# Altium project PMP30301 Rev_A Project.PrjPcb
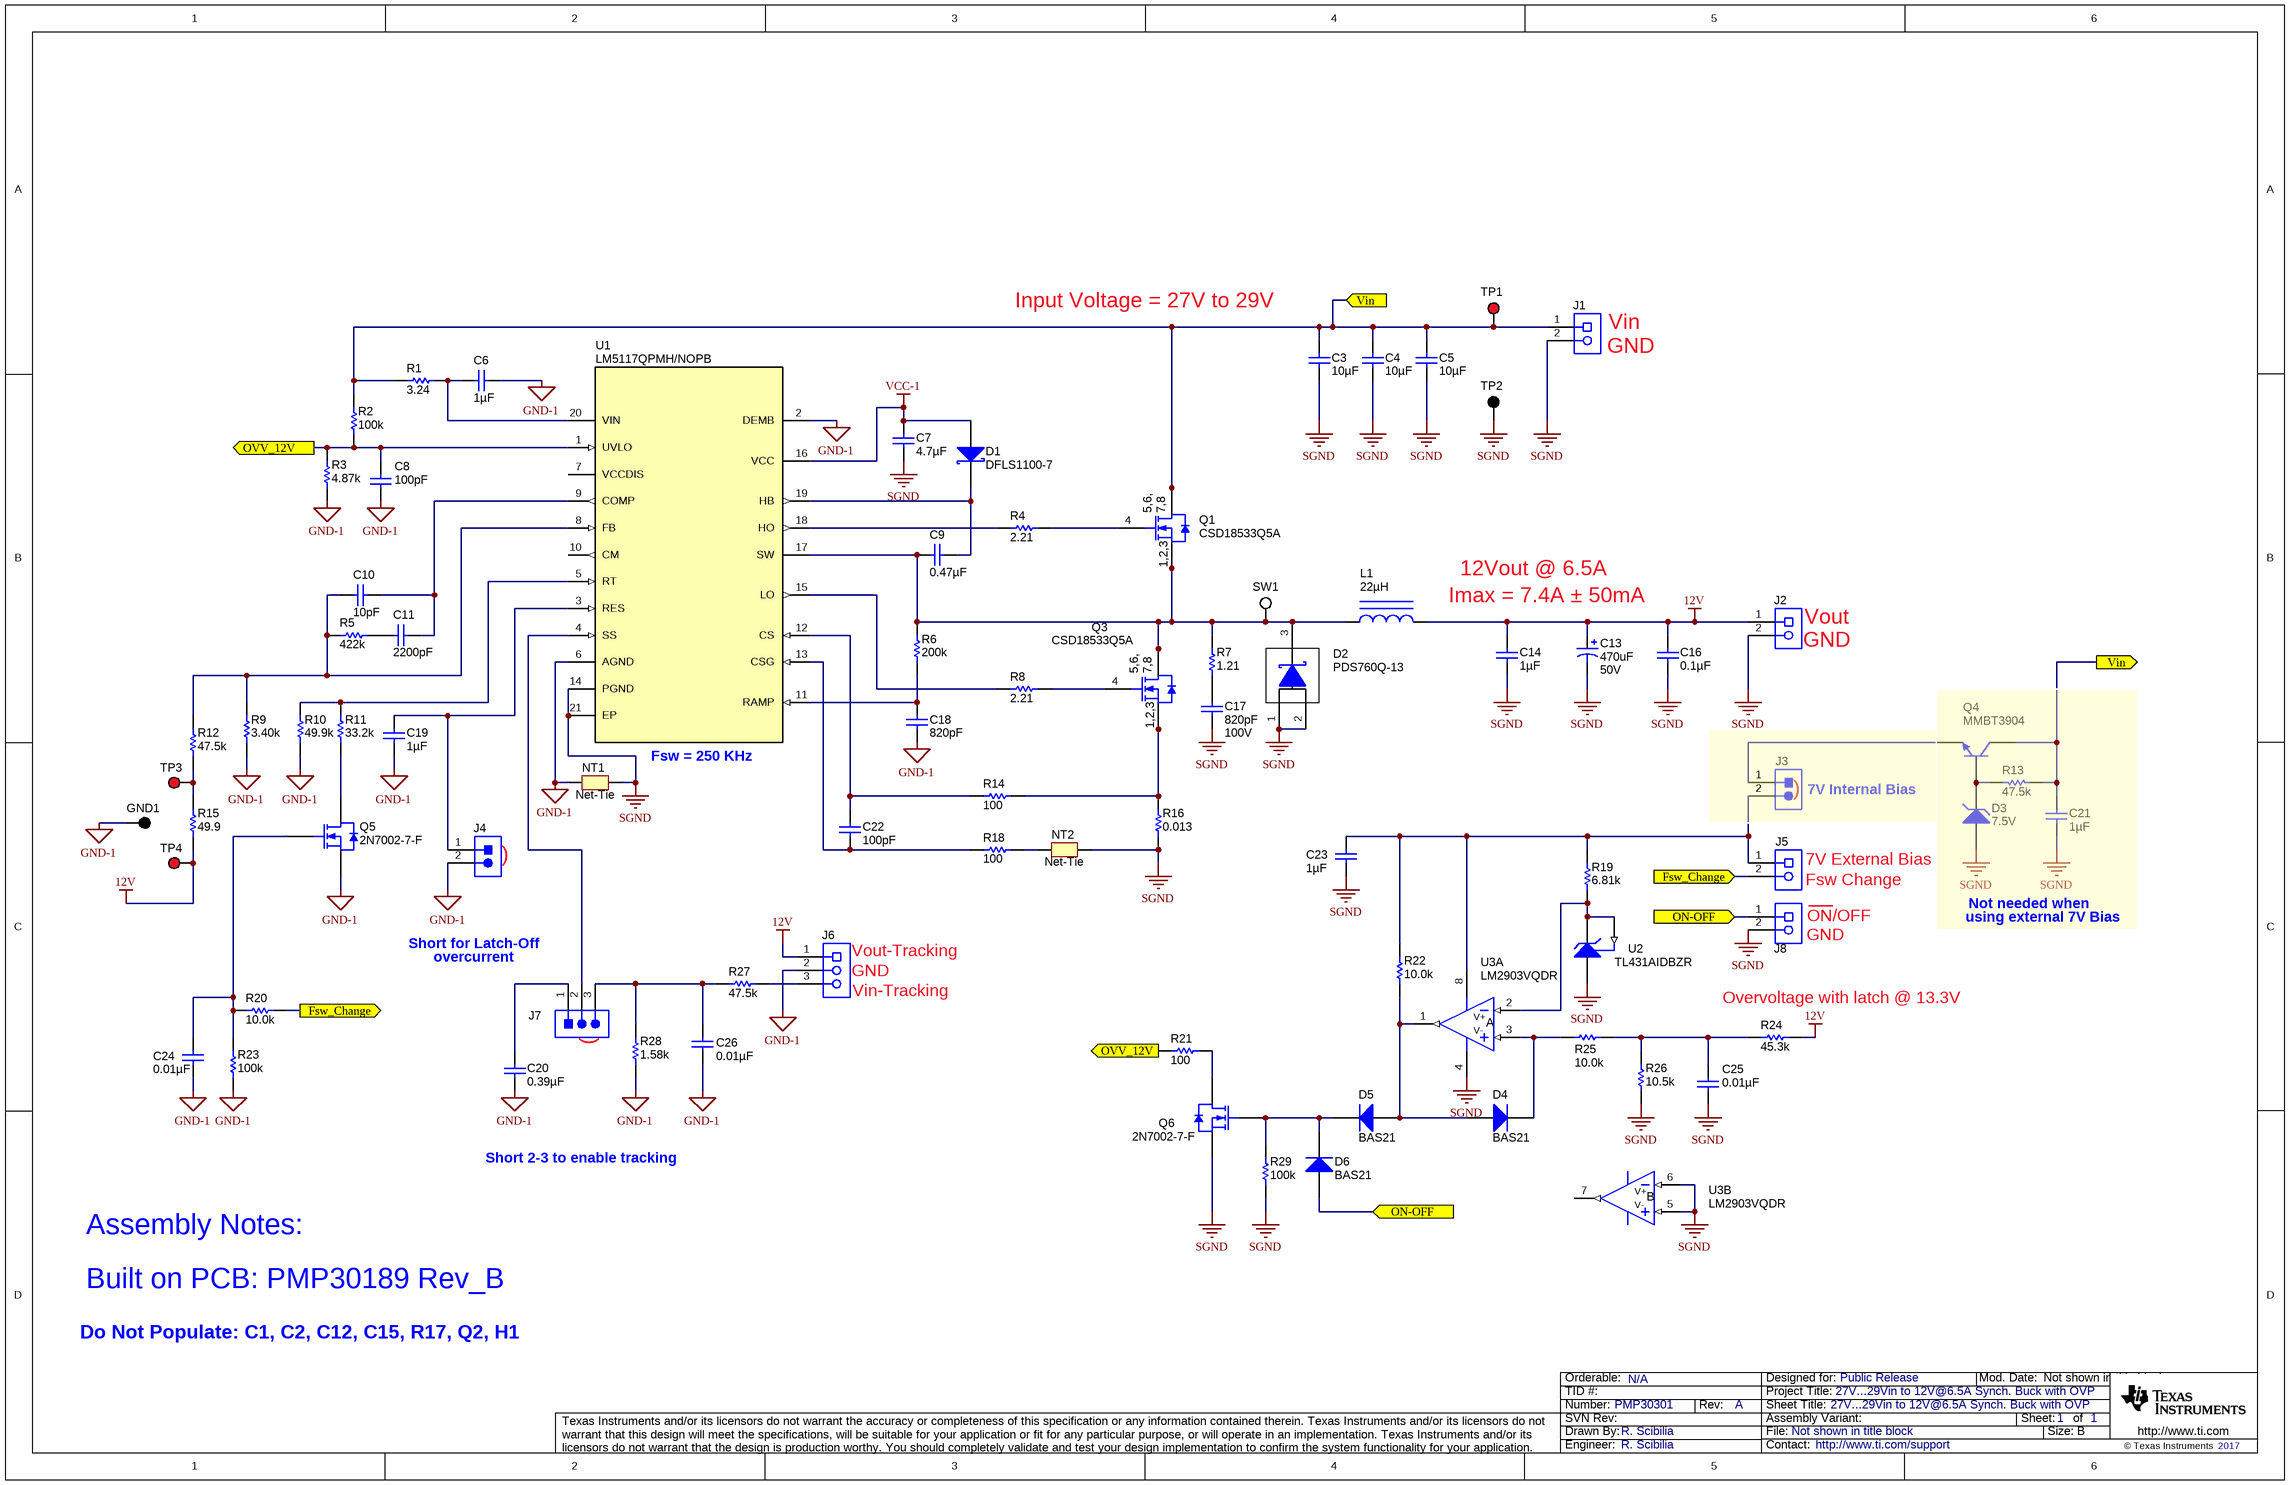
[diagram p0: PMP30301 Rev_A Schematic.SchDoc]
CopyrightYear: 2017; EVM_Orderable: N/A; PCB_Layout: PMP30189 Rev_B; PCB_Rev: B; PRJ_Customer: Public Release; PRJ_Engineer: R. Scibilia; PRJ_Number: PMP30301; PRJ_Title: 27V...29Vin to 12V@6.5A Synch. Buck with OVP; SCH_Rev: A; TechSupport: http://www.ti.com/support
1 sheet, 81 parts. Net scope: flat (ports and power ports of the same name join across sheets).
Board file: PMP30189 Rev_B PCB.PcbDoc

## Sheet PMP30301 Rev_A Schematic.SchDoc: 27V...29Vin to 12V@6.5A Synch. Buck with OVP
size 431 x 279 mm; Date: Not shown in title block; ApprovedBy: Not shown in title block; CheckedBy: Not shown in title block; Author: Not shown in title block; CompanyName: Not shown in title block; DrawnBy: R. Scibilia; Engineer: Not shown in title block; Organization: Not shown in title block; Address1: Not shown in title block; Address2: Not shown in title block; Address3: Not shown in title block; Address4: Not shown in title block; DocumentNumber: 1; Revision: Use project parameter SCH_Rev; SheetNumber: 1; SheetTotal: 1; PageSetup: Record=PageOptions¦CenterHorizontal=True¦CenterVertical=True¦PrintScale=1.00¦XCorrection=1.00¦YCorrection=1.00¦PrintKind=0¦BorderSize=5000000¦LeftOffset=0¦BottomOffset=0¦Orientation=2¦PaperLength=1000¦PaperWidth=1000¦Scale=100¦PaperSource=15¦PrintQuality=-3¦MediaType=1¦DitherType=10¦PrintScaleMode=1¦PaperKind=Letter¦PaperIndex=1

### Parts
C3  ValueDisplayed: 10µF  [1210_280]  (hidden comment: C3225X7R1H106M250AC)
C4  ValueDisplayed: 10µF  [1210_280]  (hidden comment: C3225X7R1H106M250AC)
C5  ValueDisplayed: 10µF  [1210_280]  (hidden comment: C3225X7R1H106M250AC)
C6  ValueDisplayed: 1µF  [1206]  (hidden comment: GRM31MR71H105KA88L)
C7  ValueDisplayed: 4.7µF  [0805_HV]  (hidden comment: GRM21BR71C475KA73L)
C8  ValueDisplayed: 100pF  [0603]  (hidden comment: 06035A101FAT2A)
C9  ValueDisplayed: 0.47µF  [0603]  (hidden comment: GRM188R71E474KA12D)
C10  ValueDisplayed: 10pF  [0603]  (hidden comment: GRM1885C1H100JA01D)
C11  ValueDisplayed: 2200pF  [0805_HV]  (hidden comment: GRM2165C1H222JA01D)
C13  value 470uF  Value2: 50V  [ZLH_1250x2500]  (hidden comment: 50ZLH470M12.5X20)
C14  ValueDisplayed: 1µF  [0805_HV]  (hidden comment: 08055C105KAT2A)
C16  ValueDisplayed: 0.1µF  [0805_HV]  (hidden comment: 08055C104JAT2A)
C17  value 820pF  Value2: 100V  [0603]  (hidden comment: GRM188R72A821KA01D)
C18  ValueDisplayed: 820pF  [0603]  (hidden comment: GRM1885C1H821JA01D)
C19  ValueDisplayed: 1µF  [0603]  (hidden comment: C1608X7R1C105K080AC)
C20  ValueDisplayed: 0.39µF  [0603]  (hidden comment: GRM188R71C394KA88D)
C21  ValueDisplayed: 1µF  [0805_HV]  (hidden comment: 08055C105KAT2A)
C22  ValueDisplayed: 100pF  [0603L]  (hidden comment: GRM1885C1H101JA01D)
C23  ValueDisplayed: 1µF  [0603]  (hidden comment: C1608X7R1C105K080AC)
C24  ValueDisplayed: 0.01µF  [0603]  (hidden comment: 06031C103JAT2A)
C25  ValueDisplayed: 0.01µF  [0603]  (hidden comment: 06031C103JAT2A)
C26  ValueDisplayed: 0.01µF  [0603]  (hidden comment: 06031C103JAT2A)
D1  DFLS1100-7  [powerDI123]
D2  PDS760Q-13  [PowerDI5]
D3  value 7.5V  [SOD-323F]  (hidden comment: MM3Z7V5B)
D4  value BAS21  [SOT-23L]  (hidden comment: BAS21-TP)
D5  value BAS21  [SOT-23L]  (hidden comment: BAS21-TP)
D6  value BAS21  [SOT-23L]  (hidden comment: BAS21-TP)
GND1  5001  [Keystone5001]  (value not drawn)
J1  1732720  [Phoenix_1732720]  (value not drawn)
J2  1732720  [Phoenix_1732720]  (value not drawn)
J3  800-10-002-10-001000  [Mill-Max_800-10-002-10-001000]  (value not drawn)
J4  800-10-002-10-001000  [Mill-Max_800-10-002-10-001000]  (value not drawn)
J5  39357-0002  [Molex_39357-0002]  (value not drawn)
J6  39357-0003  [Molex_39357-0003]  (value not drawn)
J7  800-10-003-10-001000  [Mill-Max_800-10-003-10-001000]  (value not drawn)
J8  39357-0002  [Molex_39357-0002]  (value not drawn)
L1  ValueDisplayed: 22µH  [WE-HCF_2013]  (hidden comment: 7443632200)
NT1  Net-Tie  [Net-Tie_10mil]  (net tie, no BOM)
NT2  Net-Tie  [Net-Tie_10mil]  (net tie, no BOM)
Q1  CSD18533Q5A  [DQJ0008A]
Q3  CSD18533Q5A  [DQJ0008A]
Q4  value MMBT3904  [SOT-23]  (hidden comment: MMBT3904LT1G)
Q5  2N7002-7-F  [SOT-23]
Q6  2N7002-7-F  [SOT-23]
R1  value 3.24  [0603]  (hidden comment: CRCW06033R24FKEA)
R2  ValueDisplayed: 100k  [0603]  (hidden comment: CRCW0603100KFKEA)
R3  ValueDisplayed: 4.87k  [0603]  (hidden comment: RC0603FR-074K87L)
R4  ValueDisplayed: 2.21  [0805_HV]  (hidden comment: RC0805FR-072R21L)
R5  ValueDisplayed: 422k  [0603]  (hidden comment: RC0603FR-07422KL)
R6  ValueDisplayed: 200k  [0603]  (hidden comment: RC0603FR-07200KL)
R7  value 1.21  [0805_HV]  (hidden comment: CRCW08051R21FKEA)
R8  ValueDisplayed: 2.21  [0805_HV]  (hidden comment: RC0805FR-072R21L)
R9  ValueDisplayed: 3.40k  [0603]  (hidden comment: RC0603FR-073K4L)
R10  ValueDisplayed: 49.9k  [0603]  (hidden comment: RC0603FR-0749K9L)
R11  ValueDisplayed: 33.2k  [0603]  (hidden comment: RC0603FR-0733K2L)
R12  ValueDisplayed: 47.5k  [0603]  (hidden comment: RC0603FR-0747K5L)
R13  ValueDisplayed: 47.5k  [0603]  (hidden comment: RC0603FR-0747K5L)
R14  ValueDisplayed: 100  [0603]  (hidden comment: RC0603FR-07100RL)
R15  ValueDisplayed: 49.9  [0603]  (hidden comment: RC0603FR-0749R9L)
R16  ValueDisplayed: 0.013  [0612]  (hidden comment: PRL1632-R013-F-T1)
R18  ValueDisplayed: 100  [0603]  (hidden comment: RC0603FR-07100RL)
R19  ValueDisplayed: 6.81k  [0603]  (hidden comment: RC0603FR-076K81L)
R20  ValueDisplayed: 10.0k  [0603]  (hidden comment: CRCW060310K0FKEA)
R21  ValueDisplayed: 100  [0603]  (hidden comment: RC0603FR-07100RL)
R22  ValueDisplayed: 10.0k  [0603]  (hidden comment: CRCW060310K0FKEA)
R23  ValueDisplayed: 100k  [0603]  (hidden comment: CRCW0603100KFKEA)
R24  ValueDisplayed: 45.3k  [0603]  (hidden comment: RC0603FR-0745K3L)
R25  ValueDisplayed: 10.0k  [0603]  (hidden comment: CRCW060310K0FKEA)
R26  ValueDisplayed: 10.5k  [0603]  (hidden comment: RC0603FR-0710K5L)
R27  ValueDisplayed: 47.5k  [0603]  (hidden comment: RC0603FR-0747K5L)
R28  ValueDisplayed: 1.58k  [0603]  (hidden comment: RC0603FR-071K58L)
R29  ValueDisplayed: 100k  [0603]  (hidden comment: CRCW0603100KFKEA)
SW1  5002  [Keystone5002]  (value not drawn)
TP1  5000  [Keystone5000]  (value not drawn)
TP2  5001  [Keystone5001]  (value not drawn)
TP3  5000  [Keystone5000]  (value not drawn)
TP4  5000  [Keystone5000]  (value not drawn)
U1  LM5117QPMH/NOPB  [PWP0020A_N]
U2  TL431AIDBZR  [DBZ0003A_N]
U3  LM2903VQDR  [D0008A_N]  (parts A,B of 2)

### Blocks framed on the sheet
): J3

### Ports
Fsw_Change, ON-OFF, OVV_12V, Vin

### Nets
12V: C13.1(+) C14.1 C16.1 J2.1 J6.1 L1.2 R15.1 R24.2 TP4.1
GND-1: C6.2 C8.2 C18.2 C19.2 C20.2 C24.1 C26.1 GND1.1 J4.2 J6.2 NT1.1 Q5.2(S) R3.1 R9.1 R10.1 R23.1 R28.1 U1.2(DEMB) U1.6(AGND)
SGND: C3.2 C4.2 C5.2 C7.2 C13.2(-) C14.2 C16.2 C17.2 C21.2 C23.2 C25.1 D2.1(A) D2.2(A) D3.2(A) J1.2 J2.2 J8.2 NT1.2 NT2.2 Q6.2(S) R16.1 R26.1 R29.1 TP2.1 U1.14(PGND) U1.21(EP) U2.3(ANODE) U3.4(V-) U3.5(IN+) U3.6(IN-)
VCC-1: C7.1 D1.2(A) U1.16(VCC)
Fsw_Change: J5.2 R20.2 ; port Fsw_Change
ON-OFF: D6.1(A) J8.1 ; port ON-OFF
OVV_12V: C8.1 R2.1 R3.2 R21.2 U1.1(UVLO) ; port OVV_12V
Vin: C3.1 C4.1 C5.1 C21.1 J1.1 Q1.5(D) Q1.6(D) Q1.7(D) Q1.8(D) Q1.9(D) Q4.3(C) R1.1 R2.2 R13.2 TP1.1 ; port Vin
NetC6_1: C6.1 R1.2 U1.20(VIN)
NetC9_1: C9.1 D1.1(K) U1.19(HB)
NetC9_2: C9.2 D2.3(K) L1.1 Q1.1(S) Q1.2(S) Q1.3(S) Q3.5(D) Q3.6(D) Q3.7(D) Q3.8(D) Q3.9(D) R6.2 R7.2 SW1.1 U1.17(SW)
NetC10_1: C10.1 C11.1 U1.9(COMP)
NetC10_2: C10.2 R5.1 R9.2 R12.2 U1.8(FB)
NetC11_2: C11.2 R5.2
NetC17_1: C17.1 R7.1
NetC18_1: C18.1 R6.1 U1.11(RAMP)
NetC19_1: C19.1 J4.1 U1.3(RES)
NetC20_1: C20.1 J7.1
NetC22_1: C22.1 R14.1 U1.12(CS)
NetC22_2: C22.2 R18.1 U1.13(CSG)
NetC23_1: C23.1 J3.2 J5.1 R19.1 R22.1 U3.8(V+)
NetC24_2: C24.2 Q5.1(G) R20.1 R23.2
NetC25_2: C25.2 R24.1 R25.1 R26.2
NetC26_2: C26.2 J7.3 R27.2 R28.2
NetD3_1: D3.1(K) Q4.1(B) R13.1
NetD4_1: D4.1(A) D5.1(A) R22.2 U3.1(OUT)
NetD4_3: D4.3(K) R25.2 U3.3(IN+)
NetD5_3: D5.3(K) D6.3(K) Q6.1(G) R29.2
NetJ3_1: J3.1 Q4.2(E)
NetJ6_3: J6.3 R27.1
NetJ7_2: J7.2 U1.4(SS)
NetNT2_1: NT2.1 R18.2
NetQ1_4: Q1.4(G) R4.2
NetQ3_1: Q3.1(S) Q3.2(S) Q3.3(S) R14.2 R16.2
NetQ3_4: Q3.4(G) R8.2
NetQ5_3: Q5.3(D) R11.1
NetQ6_3: Q6.3(D) R21.1
NetR4_1: R4.1 U1.18(HO)
NetR8_1: R8.1 U1.15(LO)
NetR10_2: R10.2 R11.2 U1.5(RT)
NetR12_1: R12.1 R15.2 TP3.1
NetR19_2: R19.2 U2.1(CATHODE) U2.2(REF) U3.2(IN-)

Not connected (* = marked no-connect by the designer): U1 7(VCCDIS) 10(CM); U3 7(OUT)

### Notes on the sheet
- (near C3) Input Voltage = 27V to 29V
- (near J1) Vin
- (near J1) GND
- 12Vout @ 6.5A
- Imax = 7.4A ± 50mA
- (near J2) Vout
- (near J2) GND
- Fsw = 250 KHz
- (near J3) 7V Internal Bias
- (near J4) )
- Fsw Change
- (near J5) 7V External Bias
- Not needed when
- Short for Latch-Off
- overcurrent
- (near J6) GND
- (near J6) Vout-Tracking
- (near J8) GND
- ON/OFF
- using external 7V Bias
- (near J6) Vin-Tracking
- (near R24) Overvoltage with latch @ 13.3V
- (
- Short 2-3 to enable tracking
- Assembly Notes:
- Built on PCB: PMP30189 Rev_B
- Do Not Populate: C1, C2, C12, C15, R17, Q2, H1

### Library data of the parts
C3-C5 = C3225X7R1H106M250AC: CAP, CERM, 10 µF, 50 V, +/- 20%, X7R, 1210; Manufacturer: TDK; Polarized: N; CompType: Capacitor; Value: 10uF; U/M: EA; Cap_F: 0.00001; Tolerance_%: 20; Value1: Unknown; VDC_V: 50; Value2: 50V; TaMin_C: -55; TaMax_C: 125; Cap_Case: 1210; SizeArea_mm2: 8; SizeAreaWB_mm2: 14.7; SizeX_mm: 3.2; SizeY_mm: 2.5; SizeZ_mm: 2.8; AEC Category: Q200
C6 = GRM31MR71H105KA88L: CAP, CERM, 1 µF, 50 V, +/- 10%, X7R, 1206; Manufacturer: MuRata; Polarized: N; CompType: Capacitor; Value: 1uF; U/M: EA; Cap_F: 0.000001; Tolerance_%: 10; Value1: Unknown; VDC_V: 50; Value2: 50V; TaMin_C: -55; TaMax_C: 125
C7 = GRM21BR71C475KA73L: CAP, CERM, 4.7 µF, 16 V, +/- 10%, X7R, 0805; Manufacturer: MuRata; Polarized: N; CompType: Capacitor; Value: 4.7uF; U/M: EA; Cap_F: 0.0000047; Tolerance_%: 10; ESR_ohm: 0.006; Value1: 0.006 ohm; VDC_V: 16; Value2: 16V; TaMin_C: -55; TaMax_C: 125; Cap_Case: 0805; SizeArea_mm2: 2.5; SizeAreaWB_mm2: 6.75; SizeX_mm: 2; SizeY_mm: 1.25; SizeZ_mm: 1.45; AEC Category: Q200
C8 = 06035A101FAT2A: CAP, CERM, 100pF, 50V, +/-1%, C0G/NP0, 0603; Manufacturer: AVX; Polarized: N; CompType: Capacitor; U/M: EA; Cap_F: 0.0000000001; Tolerance_%: 1; Value1: Unknown; VDC_V: 50; TaMin_C: -55; TaMax_C: 125
C9 = GRM188R71E474KA12D: CAP, CERM, 0.47uF, 25V, +/-10%, X7R, 0603; Manufacturer: MuRata; Polarized: N; CompType: Capacitor; U/M: EA; Cap_F: 0.00000047; Tolerance_%: 10; Value1: Unknown; VDC_V: 25; TaMin_C: -55; TaMax_C: 125
C10 = GRM1885C1H100JA01D: CAP, CERM, 10 pF, 50 V, +/- 5%, C0G/NP0, 0603; Manufacturer: MuRata; Polarized: N; CompType: Capacitor; Value: 10pF; U/M: EA; Cap_F: 0.00000000001; Tolerance_%: 5; Value1: Unknown; VDC_V: 50; Value2: 50V; TaMin_C: -55; TaMax_C: 125; SizeArea_mm2: 1.28; SizeAreaWB_mm2: 4.68; SizeX_mm: 1.6; SizeY_mm: 0.8; SizeZ_mm: 1; AEC Category: Q200
C11 = GRM2165C1H222JA01D: CAP, CERM, 2200 pF, 50 V, +/- 5%, C0G/NP0, 0805; Manufacturer: MuRata; Polarized: N; CompType: Capacitor; Value: 2200pF; U/M: EA; Cap_F: 0.0000000022; Tolerance_%: 5; Value1: Unknown; VDC_V: 50; Value2: 50V; TaMin_C: -55; TaMax_C: 125; Cap_Case: 0805; SizeArea_mm2: 2.5; SizeAreaWB_mm2: 6.75; SizeX_mm: 2; SizeY_mm: 1.25; SizeZ_mm: 1.45; AEC Category: Q200
C13 = 63ZLH470M12.5X25: CAP, AL, 470 µF, 50 V, +/- 20%, 0.027 ohm, TH; Manufacturer: Rubycon; Polarized: Y; CompType: Capacitor; ValueDisplayed: 470µF; U/M: EA; Cap_F: 0.00047; Tolerance_%: 20; VDC_V: 50; ESR_ohm: 0.027; IRMS_A: 2.05; TaMin_C: -40; TaMax_C: 105; SizeAreaWB_mm2: 210.25; SizeArea_mm2: 156.25; SizeX_mm: 12.5; AEC Category: Q200
C14 C21 = 08055C105KAT2A: CAP, CERM, 1 µF, 50 V, +/- 10%, X7R, 0805; Manufacturer: AVX; Polarized: N; CompType: Capacitor; Value: 1uF; U/M: EA; Cap_F: 0.000001; Tolerance_%: 10; Value1: Unknown; VDC_V: 50; Value2: 50V; TaMin_C: -55; TaMax_C: 125; Cap_Case: 0805; SizeArea_mm2: 2.5; SizeAreaWB_mm2: 6.75; SizeX_mm: 2; SizeY_mm: 1.25; SizeZ_mm: 1.45; AEC Category: Q200
C16 = 08055C104JAT2A: CAP, CERM, 0.1uF, 50V, +/-5%, X7R, 0805; Manufacturer: AVX; Polarized: N; CompType: Capacitor; U/M: EA; Cap_F: 0.0000001; Tolerance_%: 5; ESR_Ohm: 0.024; Value1: 0.024 ohm; VDC_V: 50; TaMin_C: -55; TaMax_C: 125; Cap_Case: 0805
C17 = GRM188R72A821KA01D: CAP, CERM, 820 pF, 100 V, +/- 10%, X7R, 0603; Manufacturer: MuRata; Polarized: N; CompType: Capacitor; U/M: EA; Cap_F: 0.00000000082; Tolerance_%: 10; Value1: Unknown; VDC_V: 100; TaMin_C: -55; TaMax_C: 125; SizeArea_mm2: 1.28; SizeAreaWB_mm2: 4.68; SizeX_mm: 1.6; SizeY_mm: 0.8; SizeZ_mm: 1; AEC Category: Q200; Green_Lifecycle: Active; Green_REACh: Passed
C18 = GRM1885C1H821JA01D: CAP, CERM, 820 pF, 50 V, +/- 5%, C0G/NP0, 0603; Manufacturer: MuRata; Polarized: N; CompType: Capacitor; Value: 820pF; U/M: EA; Cap_F: 0.00000000082; Tolerance_%: 5; Value1: Unknown; VDC_V: 50; Value2: 50V; TaMin_C: -55; TaMax_C: 125; SizeArea_mm2: 1.28; SizeAreaWB_mm2: 4.68; SizeX_mm: 1.6; SizeY_mm: 0.8; SizeZ_mm: 1; AEC Category: Q200
C19 C23 = C1608X7R1C105K080AC: CAP, CERM, 1 µF, 16 V, +/- 10%, X7R, 0603; Manufacturer: TDK; Polarized: N; CompType: Capacitor; Value: 1uF; U/M: EA; Cap_F: 0.000001; Tolerance_%: 10; ESR_ohm: 0.0057; Value1: 0.0057 ohm; VDC_V: 16; Value2: 16V; TaMin_C: -55; TaMax_C: 125; SizeArea_mm2: 1.28; SizeAreaWB_mm2: 4.68; SizeX_mm: 1.6; SizeY_mm: 0.8; SizeZ_mm: 1; AEC Category: Q200
C20 = GRM188R71C394KA88D: CAP, CERM, 0.39 µF, 16 V, +/- 10%, X7R, 0603; Manufacturer: MuRata; Polarized: N; CompType: Capacitor; Value: 0.39uF; U/M: EA; Cap_F: 0.00000039; Tolerance_%: 10; Value1: Unknown; VDC_V: 16; Value2: 16V; TaMin_C: -55; TaMax_C: 125; SizeArea_mm2: 1.28; SizeAreaWB_mm2: 4.68; SizeX_mm: 1.6; SizeY_mm: 0.8; SizeZ_mm: 1; AEC Category: Q200
C22 = GRM1885C1H101JA01D: CAP, CERM, 100pF, 50V, +/-5%, C0G/NP0, 0603; Manufacturer: MuRata; Polarized: N; CompType: Capacitor; U/M: EA; Cap_F: 0.0000000001; Tolerance_%: 5; Value1: Unknown; VDC_V: 50; TaMin_C: -55; TaMax_C: 125; Cap_Case: 0603
C24-C26 = 06031C103JAT2A: CAP, CERM, 0.01 µF, 100 V, +/- 5%, X7R, 0603; Manufacturer: AVX; Polarized: N; CompType: Capacitor; Value: 0.01uF; U/M: EA; Cap_F: 0.00000001; Tolerance_%: 5; ESR_ohm: 0.098; Value1: 0.098 ohm; VDC_V: 100; Value2: 100V; TaMin_C: -55; TaMax_C: 125
D1 = DFLS1100-7: Diode, Schottky, 100V, 1A, PowerDI123; Manufacturer: Diodes Inc.; U/M: EA; Vf_V: 0.77; Value2: 0.77V; Io_A: 1; Vr_V: 100; TJmax_C: 175; RJC_CperW: 7
D2 = PDS560-13: Diode, Schottky, 60 V, 7 A, PowerDI5; Manufacturer: Diodes Inc.; U/M: EA; Vf_V: 0.67; Value1: 7A; Value2: 0.67V; Io_A: 5; Vr_V: 60; TJmax_C: 150; SizeAreaWB_mm2: 49.56; SizeArea_mm2: 24.96; SizeX_mm: 6.4; SizeY_mm: 3.9; SizeZ_mm: 1.05; AEC Category: Q101
D3 = MM3Z7V5B: Diode, Zener, 7.5 V, 200 mW, SOD-323F; Manufacturer: Fairchild Semiconductor; SymbolCreator: a0412235; U/M: EA; Power_W: 0.2; Vz_V: 7.5; Value1: 0.2W; RJA_CperW: 595; SizeAreaWB_mm2: 7.875; SizeArea_mm2: 3.125; SizeX_mm: 2.5; SizeY_mm: 1.25; SizeZ_mm: 0.8; AEC Category: Q101
D4-D6 = BAS21-TP: Diode, P-N, 200V, 200A, SOT-23; Manufacturer: Micro Commercial Components; U/M: EA; Vf_V: 1.25; Io_A: 200; Value2: 1.25V; TJmax_C: 150; RJC_CperW: 430
GND1 TP2 = 5001: Test Point, Miniature, Black, TH; Manufacturer: Keystone; CompType: Test Point Loop; ContactFinish: Silver
J1 J2 = 1732720: Terminal Block, 2x1, 7.62mm, TH; Manufacturer: Phoenix Contact; SymbolCreator: a0412235
J3 J4 = 800-10-002-10-001000: Header, 100mil, 2x1, TH; Manufacturer: Mill-Max; SymbolCreator: a0412235
J5 J8 = 39357-0002: Terminal Block, 3.5 mm, 2x1, Tin, TH; Manufacturer: Molex; SymbolCreator: a0412235
J6 = 39357-0003: Terminal Block, 3.5 mm, 3x1, Tin, TH; Manufacturer: Molex; SymbolCreator: a0412235
J7 = 800-10-003-10-001000: Header, 100mil, 3x1, TH; Manufacturer: Mill-Max; SymbolCreator: a0799628
L1 = 7443632200: Inductor, Shielded Drum Core, Mn-Zn, 22 µH, 12 A, 0.01065 ohm, SMD; Manufacturer: Wurth Elektronik; Value: 22uH; Ind_H: 22.0E-6; Imax_A: 12; Irms: 12A @ 50C rise; Isat: 15A @ 30% inductance drop; Value2: 12A; AEC Category: Q200
NT1 NT2 = Net-Tie: Single point connection between nets.; SymbolCreator: codlsc
Q1 Q3 = CSD18533Q5A: MOSFET, N-CH, 60 V, 100 A, DQJ0008A (VSONP-8); Manufacturer: Texas Instruments; Alternate Manufacturer: None; U/M: EA; ChType: N; VdsMax_V: 60; Value1: 0.0085 ohm; Rdson45_ohm: 0.0085; Value2: 29 nC; QgTyp_nC: 29; Vgs_V: 20; IdsMax_A: 100; SizeAreaWB_mm2: 55.2; SizeArea_mm2: 29.4; SizeX_mm: 6; SizeY_mm: 4.9; SizeZ_mm: 1.1; AEC Category: Q101
Q4 = MMBT3904LT1G, ON Semiconductor: Transistor, NPN, 40 V, 0.2 A, SOT-23; CompType: BJT; PNP: 0; NPN: 1; Vceo_V: 40; Vcesat1_V: 0.3; IcRated_A: 0.2; Value1: 0.2 A; HfeMax: 300; TaMin_C: -55; TaMax_C: 150; U/M: EA; AEC Category: Q101
Q5 Q6 = 2N7002-7-F: MOSFET, N-CH, 60 V, 0.17 A, SOT-23; Manufacturer: Diodes Inc.; Alternate Manufacturer: None; U/M: EA; ChType: N; VdsMax_V: 60; Value1: 7.5 ohm; Rdson45_ohm: 7.5; Value2: 223 nC; QgTyp_nC: 223; Vgs_V: 20; IdsMax_A: 0.17
R1 = CRCW06033R24FKEA: RES, 3.24 ohm, 1%, 0.1W, 0603; Manufacturer: Vishay-Dale; CompType: Resistor; Value_Code: 3R24; Tolerance_%: 1; Power_W: 0.1; VDC_V: 75; TempCo: 100 ppm/C; EIA_Code: E96; U/M: EA
R2 R23 R29 = CRCW0603100KFKEA: RES, 100 k, 1%, 0.1 W, 0603; Manufacturer: Vishay-Dale; CompType: Resistor; Value: 100k; Res_ohm: 100000; Tolerance_%: 1; Power_W: 0.1; Value2: 0.1W; VDC_V: 75; TempCo: 100 ppm/C; EIA_Code: E96; U/M: EA
R3 = RC0603FR-074K87L: RES, 4.87 k, 1%, 0.1 W, 0603; Manufacturer: Yageo America; CompType: Resistor; Value: 4.87k; Res_ohm: 4870; Value_Code: 4k87; Tolerance_%: 1; Power_W: 0.1; Value2: 0.1W; VDC_V: 150; TempCo: 200 ppm/C; SizeArea_mm2: 1.28; SizeX_mm: 1.6; SizeY_mm: 0.8; EIA_Code: E96; U/M: EA; AEC Category: Q200
R4 R8 = RC0805FR-072R21L: RES, 2.21, 1%, 0.125 W, 0805; Manufacturer: Yageo America; CompType: Resistor; Value: 2.21; Value_Code: 2R21; Tolerance_%: 1; Power_W: 0.125; Value2: 0.125W; VDC_V: 150; TempCo: 200 ppm/C; SizeArea_mm2: 2.5; SizeX_mm: 2; SizeY_mm: 1.25; SizeZ_mm: 1.45; EIA_Code: E96; U/M: EA; AEC Category: Q200
R5 = RC0603FR-07422KL: RES, 422 k, 1%, 0.1 W, 0603; Manufacturer: Yageo America; CompType: Resistor; Value: 422k; Res_ohm: 422000; Tolerance_%: 1; Power_W: 0.1; Value2: 0.1W; VDC_V: 150; TempCo: 200 ppm/C; SizeArea_mm2: 1.28; SizeX_mm: 1.6; SizeY_mm: 0.8; EIA_Code: E96; U/M: EA; AEC Category: Q200
R6 = RC0603FR-07200KL: RES, 200 k, 1%, 0.1 W, 0603; Manufacturer: Yageo America; CompType: Resistor; Value: 200k; Res_ohm: 200000; Tolerance_%: 1; Power_W: 0.1; Value2: 0.1W; VDC_V: 150; TempCo: 200 ppm/C; SizeArea_mm2: 1.28; SizeX_mm: 1.6; SizeY_mm: 0.8; EIA_Code: E96; U/M: EA; AEC Category: Q200; Green_Lifecycle: Active; Green_REACh: Passed
R7 = CRCW08051R21FKEA: RES, 1.21 ohm, 1%, 0.125W, 0805; Manufacturer: Vishay-Dale; CompType: Resistor; Tolerance_%: 1; VDC_V: 150; Power_W: 0.125; Value_Code: 1R21; EIA_Code: E96; U/M: EA; TempCo: 100 ppm/C
R9 = RC0603FR-073K4L: RES, 3.40 k, 1%, 0.1 W, 0603; Manufacturer: Yageo America; CompType: Resistor; Value: 3.40k; Res_ohm: 3400; Value_Code: 3k40; Tolerance_%: 1; Power_W: 0.1; Value2: 0.1W; VDC_V: 150; TempCo: 200 ppm/C; SizeArea_mm2: 1.28; SizeX_mm: 1.6; SizeY_mm: 0.8; EIA_Code: E96; U/M: EA; AEC Category: Q200
R10 = RC0603FR-0749K9L: RES, 49.9 k, 1%, 0.1 W, 0603; Manufacturer: Yageo America; CompType: Resistor; Value: 49.9k; Res_ohm: 49900; Value_Code: 49k9; Tolerance_%: 1; Power_W: 0.1; Value2: 0.1W; VDC_V: 150; TempCo: 200 ppm/C; SizeArea_mm2: 1.28; SizeX_mm: 1.6; SizeY_mm: 0.8; EIA_Code: E96; U/M: EA; AEC Category: Q200; Green_Lifecycle: Active; Green_REACh: Passed
R11 = RC0603FR-0733K2L: RES, 33.2 k, 1%, 0.1 W, 0603; Manufacturer: Yageo America; CompType: Resistor; Value: 33.2k; Res_ohm: 33200; Value_Code: 33k2; Tolerance_%: 1; Power_W: 0.1; Value2: 0.1W; VDC_V: 150; TempCo: 200 ppm/C; SizeArea_mm2: 1.28; SizeX_mm: 1.6; SizeY_mm: 0.8; EIA_Code: E96; U/M: EA; AEC Category: Q200; Green_Lifecycle: Active; Green_REACh: Passed
R12 R13 R27 = RC0603FR-0747K5L: RES, 47.5 k, 1%, 0.1 W, 0603; Manufacturer: Yageo America; CompType: Resistor; Value: 47.5k; Res_ohm: 47500; Value_Code: 47k5; Tolerance_%: 1; Power_W: 0.1; Value2: 0.1W; VDC_V: 150; TempCo: 200 ppm/C; SizeArea_mm2: 1.28; SizeX_mm: 1.6; SizeY_mm: 0.8; EIA_Code: E96; U/M: EA; AEC Category: Q200
R14 R18 R21 = RC0603FR-07100RL: RES, 100, 1%, 0.1 W, 0603; Manufacturer: Yageo America; CompType: Resistor; Value: 100; Value_Code: 100R; Tolerance_%: 1; Power_W: 0.1; Value2: 0.1W; VDC_V: 150; TempCo: 200 ppm/C; SizeArea_mm2: 1.28; SizeX_mm: 1.6; SizeY_mm: 0.8; EIA_Code: E96; U/M: EA; AEC Category: Q200
R15 = RC0603FR-0749R9L: RES, 49.9, 1%, 0.1 W, 0603; Manufacturer: Yageo America; CompType: Resistor; Value: 49.9; Value_Code: 49R9; Tolerance_%: 1; Power_W: 0.1; Value2: 0.1W; VDC_V: 150; TempCo: 200 ppm/C; SizeArea_mm2: 1.28; SizeX_mm: 1.6; SizeY_mm: 0.8; EIA_Code: E96; U/M: EA; AEC Category: Q200
R16 = PRL1632-R013-F-T1: RES, 0.013, 1%, 1 W, 0612; Manufacturer: Susumu Co Ltd; CompType: Resistor; Value: 0.013; Value_Code: R013; Tolerance_%: 1; Value2: 1W; TempCo: 200 ppm/C; SizeArea_mm2: 5.12; SizeAreaWB_mm2: 10.92; SizeX_mm: 1.6; SizeY_mm: 3.2; SizeZ_mm: 0.85; EIA_Code: E96; U/M: EA; AEC Category: Q200
R19 = RC0603FR-076K81L: RES, 6.81 k, 1%, 0.1 W, 0603; Manufacturer: Yageo America; CompType: Resistor; Value: 6.81k; Res_ohm: 6810; Value_Code: 6k81; Tolerance_%: 1; Power_W: 0.1; Value2: 0.1W; VDC_V: 150; TempCo: 200 ppm/C; SizeArea_mm2: 1.28; SizeX_mm: 1.6; SizeY_mm: 0.8; EIA_Code: E96; U/M: EA; AEC Category: Q200
R20 R22 R25 = CRCW060310K0FKEA: RES, 10.0 k, 1%, 0.1 W, 0603; Manufacturer: Vishay-Dale; CompType: Resistor; Value: 10.0k; Res_ohm: 10000; Value_Code: 10k0; Tolerance_%: 1; Power_W: 0.1; Value2: 0.1W; VDC_V: 75; TempCo: 100 ppm/C; EIA_Code: E96; U/M: EA
R24 = RC0603FR-0745K3L: RES, 45.3 k, 1%, 0.1 W, 0603; Manufacturer: Yageo America; CompType: Resistor; Value: 45.3k; Res_ohm: 45300; Value_Code: 45k3; Tolerance_%: 1; Power_W: 0.1; Value2: 0.1W; VDC_V: 150; TempCo: 200 ppm/C; SizeArea_mm2: 1.28; SizeX_mm: 1.6; SizeY_mm: 0.8; EIA_Code: E96; U/M: EA; AEC Category: Q200; Green_Lifecycle: Active; Green_REACh: Passed
R26 = RC0603FR-0710K5L: RES, 10.5 k, 1%, 0.1 W, 0603; Manufacturer: Yageo America; CompType: Resistor; Value: 10.5k; Res_ohm: 10500; Value_Code: 10k5; Tolerance_%: 1; Power_W: 0.1; Value2: 0.1W; VDC_V: 150; TempCo: 200 ppm/C; SizeArea_mm2: 1.28; SizeX_mm: 1.6; SizeY_mm: 0.8; EIA_Code: E96; U/M: EA; AEC Category: Q200
R28 = RC0603FR-071K58L: RES, 1.58 k, 1%, 0.1 W, 0603; Manufacturer: Yageo America; CompType: Resistor; Value: 1.58k; Res_ohm: 1580; Value_Code: 1k58; Tolerance_%: 1; Power_W: 0.1; Value2: 0.1W; VDC_V: 150; TempCo: 200 ppm/C; SizeArea_mm2: 1.28; SizeX_mm: 1.6; SizeY_mm: 0.8; EIA_Code: E96; U/M: EA; AEC Category: Q200
SW1 = 5002: Test Point, Miniature, White, TH; Manufacturer: Keystone; CompType: Test Point Loop; ContactFinish: Silver
TP1 TP3 TP4 = 5000: Test Point, Miniature, Red, TH; Manufacturer: Keystone; CompType: Test Point Loop; ContactFinish: Silver
U1 = LM25117QPMH/NOPB: Wide Input Range Synchronous Buck Controller with Analog Current Monitor, PWP0020A (TSSOP-20); Manufacturer: Texas Instruments; SymbolCreator: a0411947; SizeArea_mm2: 41.6; SizeAreaWB_mm2: 71.4; SizeX_mm: 6.4; SizeY_mm: 6.5; SizeZ_mm: 1.2; CompType: IC; U/M: EA
U2 = TL431AIDBZR: Adjustable Precision Shunt Regulator, 34 ppm / degC, 100 mA, -40 to 85 degC, 3-pin SOT-23 (DBZ), Green (RoHS & no Sb/Br); Alternate Manufacturer: None; Alternate PartNumber: Equivalent; Manufacturer: Texas Instruments; Initial Accuracy @ 25/deg C(%): 1; Iout/Iz(Max)(mA): 100; Min Iz for Regulation(uA): 600; Rating: Catalog; SubFamily: Shunt Voltage Reference; Temp Coeff(Max)(ppm/ degree C): 92; Temp Coeff(Typ)(ppm/ degree C): 34; VO Adj(Max)(V): 36; VO Adj(Min)(V): 2.495
U3 = LM2903AVQD: Dual Comparator, D0008A; Manufacturer: Texas Instruments; CompType: OpAmp IC

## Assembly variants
001: not fitted C22 C46 C50 D13 D15 D16 R1 R2 R3 R36 R51 R54 R57 R61 R62 R63 R64 R65 R67 U6 U8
